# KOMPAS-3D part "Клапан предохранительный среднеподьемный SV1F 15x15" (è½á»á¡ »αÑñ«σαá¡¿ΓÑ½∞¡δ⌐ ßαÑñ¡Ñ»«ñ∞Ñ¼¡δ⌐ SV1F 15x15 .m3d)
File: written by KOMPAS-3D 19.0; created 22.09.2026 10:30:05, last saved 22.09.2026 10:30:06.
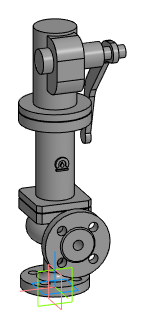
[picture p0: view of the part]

Document properties: Автор: Евгений; Полное имя файла: Z:\3.Личные\sachek\Dendor\_3D для проектировщиков\5.8 SV1F. Клапан предохранительный среднеподьемный\SV1F_STP\Клапан предохранительный среднеподьемный SV1F 15x15 .m3d

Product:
- Part/product: Клапан предохранительный среднеподьемный SV1F 15x15
    Масса: 14.3258

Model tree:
1. Операция без истории:1  (labels: Клапан предохранительный среднеподьемный SV1F 15x15)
